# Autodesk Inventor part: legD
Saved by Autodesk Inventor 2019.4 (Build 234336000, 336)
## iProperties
Created: 2020-09
Part Number: legD
Material: Generic
Document SubType Name: Modeling
Designer: Administrator
Density: 1 g/cm^3
Appearance: Default
Title: legD
Author: Administrator
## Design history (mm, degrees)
feature "Body1"
body "Solid1"
